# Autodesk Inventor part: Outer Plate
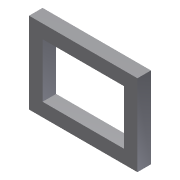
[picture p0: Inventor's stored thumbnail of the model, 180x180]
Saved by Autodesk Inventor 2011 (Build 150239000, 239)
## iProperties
Created: 2010-04
Part Number: Outer Plate
Document SubType Name: Modeling
Designer: CADSoft
Density: 1 g/cm^3
Author: CADSoft
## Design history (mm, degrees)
sketch "Sketch1"
  geometry: L1 (-40, 30)-(40, 30); L2 (40, 30)-(40, -30); L3 (40, -30)-(-40, -30); L4 (-40, -30)-(-40, 30); L5 (-30, 20)-(30, 20); L6 (30, 20)-(30, -20); L7 (30, -20)-(-30, -20); L8 (-30, -20)-(-30, 20); 1 further point
  constraints: 16 end point, 4 parallel, 2 horizontal, 2 perpendicular
  dimensions: "d0" = 80 distance of L1.start L1.end; "d1" = 60 distance of L5.start L5.end; "d2" = 10 distance between parallel lines of L4 L8; "d3" = 10 distance between parallel lines of L1 L5; "d4" = 40 distance of L7.end L5.start; "d5" = 60 distance of L3.end L1.start
extrude "Extrusion1" new body sketch "Sketch1" distance "d8" = 10; taper "d9" = 0 deg
body "Solid1"
